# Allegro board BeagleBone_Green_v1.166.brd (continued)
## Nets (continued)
MMC0_DAT1: P10.8(DAT1) R154.2 U5.G15(MMC0_DAT1/GPMC_A22/UART5_CTSN/U)
MMC0_DAT2: P10.1(DAT2) R150.2 U5.F18(MMC0_DAT2/GPMC_A21/UART4_RTSN/T)
MMC0_DAT3: P10.2(CD/DAT3) R155.2 U5.F17(MMC0_DAT3/GPMC_A20/UART4_CTSN/T)
MMC1_CLK: P8.21(11) R110.2 U5.U9(GPMC_CSN1/GPMC_CLK/MMC1_CLK/PRT) U13.M6(CLK)
MMC1_CMD: P8.20(35) R109.2 U5.V9(GPMC_CSN2/GPMC_BE1N/MMC1_CMD/PR) U13.M5(CMD)
MMC1_DAT0: P8.25(13) R101.2 U5.U7(GPMC_AD0/MMC1_DAT0//////GPIO1_0) U13.A3(DAT0)
MMC1_DAT1: P8.24(37) R102.2 U5.V7(GPMC_AD1/MMC1_DAT1//////GPIO1_1) U13.A4(DAT1)
MMC1_DAT2: P8.5(3) R103.2 U5.R8(GPMC_AD2/MMC1_DAT2//////GPIO1_2) U13.A5(DAT2)
MMC1_DAT3: P8.6(28) R104.2 U5.T8(GPMC_AD3/MMC1_DAT3//////GPIO1_3) U13.B2(DAT3)
MMC1_DAT4: P8.23(12) R105.2 U5.U8(GPMC_AD4/MMC1_DAT4//////GPIO1_4) U13.B3(DAT4)
MMC1_DAT5: P8.22(36) R106.2 U5.V8(GPMC_AD5/MMC1_DAT5//////GPIO1_5) U13.B4(DAT5)
MMC1_DAT6: P8.3(2) R107.2 U5.R9(GPMC_AD6/MMC1_DAT6//////GPIO1_6) U13.B5(DAT6)
MMC1_DAT7: P8.4(27) R108.2 U5.T9(GPMC_AD7/MMC1_DAT7//////GPIO1_7) U13.B6(DAT7)
MODE2: R113.1 R138.2 U14.15(COL/CRS_DV/MODE2)
OSC1_IN: C21.2 U5.A6(OSC1_IN) Y1.1
OSC1_OUT: C22.2 U5.A4(OSC1_OUT) Y1.4
P_BYPASS: C4.2 U2.47(BYPASS)
P_INT_LDO: C3.2 U2.48(INT_LDO)
P_L1: L1.1 U2.20(L1)
P_L2: L2.1 U2.23(L2)
P_L3: L3.1 U2.31(L3)
PHY_VDDCR: C134.1 C136.1 U14.6(VDDCR)
PHY_XTAL1: C143.1 R141.2 R142.1 Y3.1
PHY_XTAL2: R141.1 R143.1 U14.4(XTAL2)
PHYX: C142.1 R143.2 Y3.2
PMIC_INT: R1.2 U2.45(INT) U5.B18(NNMI)
PMIC_PGOOD: U2.26(PGOOD) U5.B15(PORZN) U16.2(A)
PMIC_POWR_EN: U2.9(PWR_EN) U5.C6(PMIC_POWER_EN)
PROC_A15: R18.1 U5.A15(EVENT_INTR0/TIMER4/CLKOUT1/SPI1)
PWR_BUT: P9.9(5) S3.2(B1) S3.4(B2) U2.25(PB_IN)
PWR_LEDR: D1.1(C) R12.2
RBIAS: R144.1 U14.32(RBIAS)
RCLKIN: C161.1 R140.2 R142.2 U14.5(XTAL1/CLKIN)
REFCLKO: C162.2 R118.1 R124.2 R131.2 U14.7(RXCLK/PHYAD1)
RXD0/MODE0: R112.1 R128.2 U14.11(RXD0/MODE0)
RXD1/MODE1: R114.1 R127.2 U14.10(RXD1/MODE1)
RXD2/RMIISEL: R117.1 R126.2 U14.9(RXD2/RMIISEL)
RXD3/PHYAD2: R116.1 R125.2 U14.8(RXD3/PHYAD2)
RXDV: R129.2 U14.26(RXDV)
RXER/PHYAD0: R115.1 R133.2 U14.13(RXER/RXD4/PHYAD0)
RXN: C138.1 P5.2(RD-) R121.1 U14.30(RXN)
RXP: C137.1 P5.1(RD+) R120.1 U14.31(RXP)
SPI1_CS0: P9.28(39) U5.C12(MCASP0_AHCLKR/EHRPWM0_SYNCI_O/M)
SPI1_D0: P9.29(15) U5.B13(MCASP0_FSX/EHRPWM0B//SPI1_D0/MM)
SPI1_D1: P9.30(40) U5.D12(MCASP0_AXR0/EHRPWM0_TRIPZONE_IN)
SPI1_SCLK: P9.31(16) U5.A13(MCASP0_ACLKX/EHRPWM0A//SPI1_SCL)
SYS_5V: C7.2 C8.2 C10.2 C13.2 C17.1 C34.1 P9.7(4) P9.8(29) R71.1 R72.1 R73.1 R74.1 U2.2(VINLDO) U2.7(SYS1) U2.8(SYS2) U2.21(VIN_DCDC1) U2.22(VIN_DCDC2) U2.32(VIN_DCDC3) U2.39(LDO3_IN) U2.42(LDO4_IN) U4.2(IN) U8.2(IN1) U8.3(IN2)
SYS_RESETN: C24.1 C30.1 P2.15(SRST) P9.10(30) R14.2 S1.2(B1) S1.4(B2) U5.A10(NRESET_INOUT) U14.19(NRST) U16.4(Y)
TCT_RCT: C141.1 P5.4(RCT) P5.5(TCT) R137.1
TESTOUT: TP3.1(TP) U5.A3(TESTOUT)
TIMER4: P8.7(4) U5.R7(GPMC_ADVN_ALE/TIMER4/GPIO2_2)
TIMER5: P8.9(5) U5.T6(GPMC_BE0N_CLE/TIMER5/GPIO2_5)
TIMER6: P8.10(30) U5.U6(GPMC_WEN/TIMER6/GPIO2_4)
TIMER7: P8.8(29) U5.T7(GPMC_OEN_REN/TIMER7/EMU4/GPIO2_)
TXCLK: R134.2 U14.20(TXCLK)
TXN: C140.1 P5.6(TD-) R123.1 U14.28(TXN)
TXP: C139.1 P5.3(TD+) R122.1 U14.29(TXP)
U5_H18: R28.1 U5.H18(RMII1_REFCLK/XDMA_EVENT_INTR2/S)
U5_R13: R160.1 U5.R13(GPMC_A0/GMII2_TXEN/RGMII2_TCTL/)
U5_T13: R161.1 U5.T13(GPMC_CSN3/MMC2_CMD/PR1_MDIO_DAT)
UART0_RX: U5.E15(UART0_RXD/SPI1_CS0/DCAN0_TX/I2C) U15.6(1Y)
UART0_TX: U5.E16(UART0_TXD/SPI1_CS1/DCAN0_RX/I2C) U15.5(2A)
UART1_RXD: P9.26(38) U5.D16(UART1_RXD/MMC1_SDWP/DCAN1_TX/I2)
UART1_TXD: P9.24(37) U5.D15(UART1_TXD/MMC2_SDWP/DCAN1_RX/I2)
UART2_RXD: J5.1 P9.22(36) U5.A17(SPI0_SCLK/UART2_RXD/I2C2_SDA/EH)
UART2_TXD: J5.2 P9.21(11) U5.B17(SPI0_D0/UART2_TXD/I2C2_SCL/EHRP)
UART4_RXD: P9.11(6) U5.T17(GPMC_WAIT0/GM112_CRS/GPMC_CSN4/)
UART4_TXD: P9.13(7) U5.U17(GPMC_WPN/GMII2_RXERR/GPMC_CSN5/)
USB0_DM: P4.2(D-) U5.N18(USB0_DM) U10.2(D-)
USB0_DP: P4.3(D+) U5.N17(USB0_DP) U10.1(D+)
USB0_ID: P4.4(ID) U5.P16(USB0_ID) U10.3(ID)
USB1_DM: P3.2(P2) U5.R18(USB1_DM) U9.2(D-)
USB1_DP: P3.3(P3) U5.R17(USB1_DP) U9.1(D+)
USB1_DRVVBUS: R53.1 U5.F15(USB1_DRVVBUS/GPIO3_13) U8.4(EN)
USB1_ID: R49.2 U5.P17(USB1_ID)
USB1_OCN: R52.2 U5.T16(GPMC_A10/GMII2_RXD1/RGMII2_RD1/) U8.5(O\C\)
USB1_PWR: C35.1 FB7.1 FB8.2 U8.6(OUT3) U8.7(OUT2) U8.8(OUT1) U9.6(VBUS)
USB1_VBUS: FB8.1 U5.T18(USB1_VBUS)
USB_DC: C1.2 C36.1 P4.1(VB) R159.1 R168.1 U2.12(USB) U10.6(VBUS)
USR0: Q1.2(5) R76.1 U5.V15(GPMC_A5/GMII2_TXD0/RGMII2_TD0/R)
USR1: Q1.5 R77.1 U5.U15(GPMC_A6/GMII2_TXCLK/RGMII2_TCLK)
USR2: Q2.2(5) R78.1 U5.T15(GPMC_A7/GMII2_RXCLK/RGMII2_RCLK)
USR3: Q2.5 R79.1 U5.V16(GPMC_A8/GMII2_RXD3/RGMII2_RD3/M)
VDCDC1: L1.2 R6.1 U2.19(VDCDC1)
VIO: R7.2 U2.18(VIO) U16.5(VCC)
VLDO1: R5.1 R7.1 R8.1 U2.3(VLDO1)
VREFP_ADC: C31.1 C32.1 C33.1 R27.2 U5.B9(VREFP)
VRTC: C16.1 C105.1 R5.2 R26.1 U5.D7(VDDS_RTC)
WAKEUP: R26.2 U2.13(WAKEUP) U5.C5(EXT_WAKEUP)
WP: R156.2 TP4.1(TP) U7.5(WP)
XDMA_EVENT_INTR0: P2.17(EMU2) R18.2
YEL_C: P5.11(YELC) R130.2
YELA: C164.1 C166.1 P5.12(YELA) R135.1 U14.2(LED2/NINTSEL)
ZQ: R99.2 U12.L8(ZQ)
N21757673: C19.1 R10.1 R11.2 U4.4(ADJ)
N21769115: R75.2 S2.1(A1) S2.3(A2)
N22155575: R159.2 U5.P15(USB0_VBUS)
N22248684: R167.1 Y4.3(CLK)
N22287501: R162.1 U3.4(Y)
N22287555: U3.2(A) U5.R14(GPMC_A4/GMII2_TXD1/RGMII2_TD1/R)
N22420400: TP5.1(TP) U2.4(BAT1) U2.5(BAT2)
N22420444: TP6.1(TP) U2.6(BAT_SENSE)
N22420447: TP7.1(TP) U2.11(TS)
N22488252: TP9.1(TP) U5.E17(UART0_RTSN/UART4_TXD/DCAN1_RX/I)
N22648410: C25.1 R17.1 U17.1(XIN/CXIN) Y2.2
N22648422: C26.1 R17.2 U17.2(CKOUT) Y2.1
N22649826: R171.2 U17.3(SSON)
N22650321: R172.2 R174.1 U17.6(ADS0)
N22650344: R173.1 R175.2 U17.7(ADS1)
N22650388: U5.V10(OSC0_IN) U17.5(MOD OUT)

Pads without a net: J1 2 3 6; NOREF#6 1; NOREF#8 1; NOREF#11 1; NOREF#12 1; NOREF#15 1; NOREF#19 1; NOREF#25 1; NOREF#32 1; NOREF#33 1; NOREF#34 1; NOREF#35 1; NOREF#37 1; NOREF#38 1; NOREF#40 1; P2 6; P5 7; U2 14 15 16 17 33 34 35 36 37 38 44; U3 1; U5 E18 F16 M5 M15 P18 U11; U9 3 5; U10 5; U12 J1 J9 L1 L9; U13 A1 A2 A6 A7 A8 A9 A10 A11 A12 A13 A14 B1 B7 B8 B9 B10 B11 B12 B13 B14 C1 C3 C5 C7 C8 C9 C10 C11 C12 C13 C14 D1 D2 D3 D4 D12 D13 D14 E1 E2 E3 E5 E8 E9 E10 E12 E13 E14 F1 F2 F3 F10 F12 F13 F14 G1 G2 G3 G10 G12 G13 G14 H1 H2 H3 H5 H12 H13 H14 J1 J2 J3 J5 J12 J13 J14 K1 K2 K3 K6 K7 K10 K12 K13 K14 L1 L2 L3 L12 L13 L14 M1 M2 M3 M7 M8 M9 M10 M11 M12 M13 M14 N1 N3 N6 N7 N8 N9 N10 N11 N12 N13 N14 P1 P2 P7 P8 P9 P10 P11 P12 P13 P14; U16 1; Y1 2 3

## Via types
v1: diameter 0.457, hole 0.203, TOP to BOTTOM, 820 vias
v2: diameter 0.559, hole 0.305, TOP to BOTTOM, 28 vias

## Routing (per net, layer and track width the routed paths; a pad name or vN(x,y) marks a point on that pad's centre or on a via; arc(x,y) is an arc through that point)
DGND: length 353.8
  TOP w0.076: U13.N2 28.49,109.79 28.23,110.04 27.89,110.04 27.88,110.05 27.73,110.05
  TOP w0.178: U13.N5 U13.P4
  TOP w0.191: U10.4 v1(15.49,106.54)
  TOP w0.203: 27.73,110.05 27.57,110.05 v1(27.41,110.21) ; U13.C4 v1(32.99,108.29) ; U13.K8 v1(29.46,106.79) ; v1(31.24,105.18) 31.24,105.26 30.99,105.51 U13.H10 ; U13.E7 32.67,107.11 v1(32.99,107.11) ; v2(25.27,80.37) 25.65,80.37 25.85,80.17 U2.30 ; U13.G5 31.35,108.43 31.19,108.59 v1(31.19,108.81) ; v1(27.43,107.65) 27.57,107.79 U13.P6 ; U2.41 v1(24.86,84.75) ; U13.P4 26.98,108.79 v1(26.49,109.27)
  TOP w0.254: U12.B9 v1(68.5,95.49) U12.A9 ; U5.H7 v1(49.52,92.74) ; v1(47.92,95.14) U5.K9 ; v1(68.5,85.09) U12.P9 ; U5.L12 v1(44.72,95.94) U5.L13 ; U5.J11 v1(45.52,93.54) ; v1(44.72,92.74) U5.H12 ; U5.A18 v1(39.92,87.13) ; v1(67.7,93.09) U12.E8 ; U5.M9 v1(47.92,96.74) U5.M8 ; U5.F8 v1(47.92,91.94) U5.G9 ; v1(61.3,95.49) U12.B1 ; U12.G1 60.71,92.08 60.71,92.43 61.09,92.81 61.58,92.81 U12.E1 v1(62.1,92.29) ; v1(68.5,86.69) U12.M9 ; v1(54,101.7) 53.92,101.62 U5.V1 ; v1(44.72,91.94) U5.G12 45.28,92.18 45.76,92.18 U5.G11 ; U5.A1 v1(53.92,86.84) ; v1(46.32,96.74) U5.M10 ; v1(48.72,93.54) U5.J8 ; U5.L10 v1(46.32,95.14) ; v1(46.32,95.14) U5.K10 ; v1(46.32,95.14) U5.K11 ; U12.F9 v1(68.5,91.49) U12.G9 ; v1(48.72,92.74) U5.H8 ; v1(62.1,89.09) U12.J2 ; U5.G8 v1(47.92,92.74) U5.H9 ; U5.M12 v1(45.52,95.94) U5.L11 ; v1(61.3,86.69) U12.M1 ; v1(47.92,93.54) U5.J9 ; U5.N10 v1(46.32,97.54) U5.N11 ; v1(62.9,95.49) U12.B3 ; v1(61.3,83.49) U12.T1 ; U12.D1 v1(62.1,93.09) U12.E2 ; U5.M7 v1(49.52,95.94) U5.M6 ; v1(67.7,91.49) U12.G8 ; v1(49.52,93.54) U5.J7 U5.K7 ; U5.H10 v1(46.32,93.54) U5.J10 ; U5.H6 v1(50.32,93.54) U5.J6 ; v1(68.5,83.49) U12.T9 ; v1(49.52,97.54) U5.N7 ; U5.N14 v1(43.12,96.74) U5.M14 ; U5.V18 40.39,101.2 v1(40.39,101.96) ; v1(67.7,93.89) U12.D8 ; v1(61.3,85.09) U12.P1 ; v1(67.7,89.09) U12.J8
  TOP w0.381: C57.1 v1(56.26,113.64) ; C162.1 R118.2 31.93,90.02 v1(32.08,89.87) ; v1(79.8,80.67) J4.4 v1(75.77,80.67) ; 40.13,104.75 40,104.88 C159.2 38.99,104.88 38.73,105.13 ; S1.1 v1(9.35,116.48) ; C153.2 84.2,108.69 v1(84.46,108.94) ; v1(28.38,72.24) 28.38,73.32 C12.1 28,73.44 27.69,73.13 27.69,72.3 v1(27.75,72.24) ; R170.2 23.01,102.82 v1(22.71,103.12) ; v1(23.49,86.46) 22.86,85.83 22.86,85.45 ; v1(54.48,107.8) 54.36,107.92 R81.2 ; v1(57.4,76.53) 57.12,76.81 57.02,76.81 C155.1 C96.1 57.89,77.95 57.91,77.93 ; C18.2 v1(19.68,84.68) ; v1(17.32,108.99) 17.81,108.99 18.02,108.78 Q2.1 ; v1(22.99,72.36) 22.99,73.25 C1.1 22.35,73.38 v1(22.35,72.36) ; C154.2 v1(80.14,108.56) ; R94.2 75.57,111.35 v1(75.18,110.97) ; S3.1 9.35,108.89 v1(10.03,109.58) ; S2.4 v1(73.53,107.87) ; Q1.1 20.69,108.75 v1(19.96,109.47) 19.84,109.6 19.48,109.6 19.32,109.76 Q2.4 ; 23.37,108.18 R77.2 23.11,109.58 22.73,109.96 22.73,110.46 v1(22.61,110.59) 22.1,110.59 21.99,110.48 Q1.4 ; S3.3 v1(10.29,104.85) ; v1(73.15,110.85) 73.79,111.48 R92.2 R93.2 ; R78.2 R79.2 21.97,105.23 v1(22.48,104.72) ; U3.3 v1(42.37,110.85) ; v1(35.69,71.6) C29.2 ; R25.2 37.78,74.21 37.46,73.89 v1(37.46,73.7) ; R80.2 v1(55.37,110.97) ; U16.3 32.28,74.81 32.05,75.03 v1(31.65,75.03) ; S1.3 v1(9.35,115.6) ; v1(47.75,77.71) R165.2 ; C61.1 v1(76.45,113.51) ; v1(77.85,110.85) 77.34,111.35 R95.2 ; R84.2 v1(57.66,110.85) ; S2.2 v1(77.09,107.87) ; J5.4 v1(79.93,95.53)
  TOP w0.889: Y4.2 42.18,107.79 ; Y4.2 42.82,107.23 ; Y4.2 42.18,106.67
  LYR2_GND w0.889: 76.23,67.76 P9.45 77.7,67.76 ; 11.02,72.77 P3.4 ; P3.4 12.34,74.1 ; P3.4 11.02,74.1 ; P3.4 12.34,72.77 ; 17.81,91.26 P5.8 ; P5.8 19.28,91.26 ; P5.8 19.28,89.79 ; P5.8 17.81,89.79 ; 42.98,73.71 J1.1 ; J1.1 42.98,71.78 ; J1.1 44.91,71.78 ; P8.1 22.05,116.26 ; P8.1 22.05,114.32 ; P8.1 20.12,116.26 ; P8.1 20.12,114.32 ; P9.2 21.82,68.84 ; P9.2 20.35,70.3 ; P9.2 21.82,70.3 ; P9.2 20.35,68.84 ; 20.12,68 P9.1 22.05,68 ; P9.44 75.16,70.3 ; P9.44 73.69,68.84 ; P9.44 73.69,70.3 ; P9.44 75.16,68.84 ; 60.84,76.53 TP1.1 ; TP1.1 62.3,75.06 ; TP1.1 62.3,76.53 ; TP1.1 60.84,75.06 ; 75.16,67.76 P9.43 73.69,67.76 ; 21.82,117.1 P8.2 20.35,117.1 ; TP8.1 19.4,72.52 ; TP8.1 19.4,73.99 ; TP8.1 17.94,72.52 ; TP8.1 17.94,73.99 ; 76.23,70.3 P9.46 ; P9.46 77.7,70.3 ; P9.46 76.23,68.84 ; P9.46 77.7,68.84
  LYR5_PWR w0.889: 73.69,70.3 P9.44 ; P9.44 73.69,68.84 ; P9.44 75.16,68.84 ; P9.44 75.16,70.3 ; P9.46 77.7,68.84 ; P9.46 76.23,68.84 ; P9.46 76.23,70.3 ; P9.46 77.7,70.3 ; 76.23,67.76 P9.45 77.7,67.76 ; 73.69,67.76 P9.43 75.16,67.76
  BOTTOM w0.191: v1(30.61,97.83) 30.61,97.48 30.73,97.35 32.26,97.35 32.38,97.22 R115.2 ; v1(46.32,89.54) 46.32,89.42 47.11,88.63 C88.2
  BOTTOM w0.203: C100.2 50.21,91.07 50.66,90.62 50.83,90.62 v1(51.12,90.34)
  BOTTOM w0.254: 54.52,82.35 R30.1 53.68,82.35 ; v1(57.4,76.53) 57.4,76.81 57.15,77.06 C155.1 ; C130.2 36.37,105.84 v1(36.98,105.84) ; C70.1 44.02,91.24 v1(44.72,91.94) v1(44.72,92.74) ; v1(14.22,80.87) 14.61,80.48 U9.4 ; C127.2 v1(26.8,105.77) ; U15.1 51.68,75.81 51.43,76.05 51.43,77.06 51.68,77.3 U15.4 53.48,77.3 54.23,76.56 54.23,75.67 54.61,75.29 v1(55.88,75.29) ; C129.2 32.51,106.53 32.99,107.01 v1(32.99,107.11) ; 15.49,82.14 v1(14.61,82.14) ; v1(29.46,106.79) 29.49,106.81 29.62,106.81 30.35,107.54 C128.2
  BOTTOM w0.305: v1(46.32,93.54) 46.98,93.54 C49.2 ; C47.2 47.22,95.14 v1(47.92,95.14) ; C94.2 v1(45.52,95.94) ; C98.2 50.32,94.23 v1(50.32,93.54) ; v2(52.32,110.46) R29.1 v2(53.09,111.35) ; v1(46.32,95.14) 46.02,94.84 C46.2 ; C41.2 43.12,97.43 v1(43.12,96.74) 43.12,96.04 C66.2 ; C50.2 v1(48.72,92.74) ; v1(47.92,96.74) 47.62,97.03 C42.2 ; C63.2 45.41,91.94 v1(44.72,91.94) ; C72.1 47.62,91.64 v1(47.92,91.94) ; C43.2 48.83,97.54 v1(49.52,97.54) C73.1 ; C48.2 49.23,93.83 v1(49.52,93.54) ; v1(49.52,95.94) C97.2 ; C99.2 v1(49.52,92.74) ; C60.1 v1(44.72,92.74)
  BOTTOM w0.381: v1(6.99,74.9) 6.73,74.9 6.31,74.48 U8.1 ; v1(50.61,83.54) C104.2 C92.2 ; v1(50.61,83.54) 52.27,83.54 52.51,83.79 R54.1 ; v1(50.61,83.54) R164.2 ; v1(37.46,81.32) P2.16 39.41,81.25 40.75,81.25 40.89,81.11 41.63,81.11 41.93,81.4 41.93,82.89 40.96,83.86 P2.20 ; C80.2 42.72,102.9 42.75,102.93 v1(42.75,103.12) ; C68.1 v1(50.32,103.23) ; v1(20.09,113.74) 19.56,113.21 U4.6 ; v1(24.99,105.16) 24.89,105.26 C126.1 ; 27.3,95.61 27.56,95.35 C136.2 ; v1(33.78,102.27) C77.2 ; C141.2 v1(12.06,95.61) ; C28.2 v1(58.55,93.54) ; v1(36.96,99.03) 36.45,99.03 C78.2 ; v1(3.3,82.91) 3.68,82.52 R12.1 ; C17.2 21.72,103.15 v1(21.18,102.62) ; C122.1 71.24,81.95 v1(71.25,81.95) ; C135.2 29.21,98.78 29.24,98.76 v1(29.39,98.76) ; v1(20.27,102.51) 20.57,102.82 C20.2 ; R88.2 v1(66.42,108.43) ; C75.1 v1(54.48,113.51) ; v1(19.53,114.58) 19.3,114.58 18.29,113.56 U4.5 ; R100.2 C124.2 v1(64.39,86.33) ; U7.2 31.31,87.03 30.86,86.59 v1(30.86,85.83) ; C112.2 v1(58.55,85.89) ; C71.1 40.26,102.08 v1(40.39,101.96) ; 34.42,85.45 35.18,85.45 ; 34.42,85.45 34.42,86.33 C62.1 35.18,86.33 35.18,85.45 ; 34.42,85.45 v1(34.42,85.45) ; 35.18,85.45 C64.2 ; C117.2 70.75,90.69 v1(71.27,90.17) ; C120.2 v1(71.25,85.89) ; C45.2 C87.2 38.95,95.9 38.26,95.9 v1(38.23,95.94) ; v1(17.93,102.54) 17.53,102.95 R10.2 ; U4.7 v1(20.83,113.51) ; C119.2 v1(71.25,89.49) ; v1(13.46,98.78) 13.42,98.78 13.17,99.03 13.17,99.2 C137.2 ; P10.9 v1(73.99,99.07) ; C116.2 v1(71.37,93.7) ; C24.2 C30.2 31.39,75.29 v1(31.65,75.03) ; C142.2 v1(23.3,90.4) ; C92.2 v1(49.66,83.65) ; C92.2 C105.2 C89.2 C91.2 C90.2 C59.2 ; C158.2 41.91,112.62 42.37,112.16 v1(42.37,110.85) ; C161.2 28.57,92.3 v1(29.34,92.3) ; R53.2 v1(4.32,70.33) ; C111.2 v1(58.55,88.29) ; P2.4 v1(37.46,73.7) ; v1(7.62,95.35) 6.79,95.35 R136.1 6.79,94.59 v1(7.62,94.59) ; v1(7.62,95.35) v1(7.62,94.59) ; v1(7.62,95.35) R132.1 ; v1(51.56,103.23) 51.92,102.87 C74.1 ; v1(7.62,94.59) R130.1 R135.2 ; C35.2 v1(7.49,81.13) ; C113.2 v1(58.55,84.29) ; R96.1 v1(71.25,88.29) ; C125.2 v1(33.78,113.39) ; R145.2 v1(33.15,99.73) ; P2.8 37.53,76.24 v1(37.46,76.3) 37.46,77.26 37.71,77.51 P2.10 P2.12 ; C86.2 38.98,100.37 38.61,100.74 38.15,100.74 v1(38.1,100.79) ; R83.2 62.1,108.66 v1(62.41,108.36) ; R82.2 60.81,109.19 v1(60.5,108.89) ; C58.2 C106.2 45.36,102.44 45.85,101.96 v1(47.12,101.96) C56.1 ; C54.2 C79.2 C69.1 ; C54.2 v1(38.23,91.94) ; C54.2 C44.2 ; C61.1 v1(76.45,113.51) ; v1(14.07,108.81) C36.2 14.86,109.32 v1(14.61,109.58) ; R87.2 v1(65.53,108.43) ; C84.2 48.39,102.9 v1(48.72,103.23) 49.28,102.67 C81.2 ; R99.1 v1(71.25,87.09) ; v1(67.7,89.09) U12.J8 C123.2 ; v1(38.23,98.78) 38.54,99.1 R49.1 ; v1(34.42,100.69) C67.2 C38.2 ; v1(71.32,91.06) 71.5,91.24 C118.1 ; C108.2 v1(58.55,94.69) ; R30.1 C102.2 ; R89.2 v1(67.69,108.46) ; C121.2 v1(71.25,84.29) ; v1(4.47,110.82) 4.78,110.52 6.08,110.52 P4.5 ; R117.2 R116.2 v1(33.15,93.07) ; C110.2 v1(58.55,90.69) 58.46,90.78 R22.1 ; C114.2 v1(71.25,96.29) ; v1(16.74,76.94) C2.1 16.18,78.03 15.67,77.52 v1(15.67,76.99) ; C85.2 C83.2 C82.2 38.35,89.89 38.23,90.01 v1(38.23,90.01) ; C139.2 v1(12.06,96.88) ; C138.2 v1(12.06,98.15) ; C109.2 v1(58.55,92.29) ; C19.2 18.41,102.92 v1(18.82,102.51) ; R85.2 v1(63.37,108.46) ; R91.2 v1(69.16,109.19) R90.2 ; C115.2 v1(71.25,94.69) ; R86.2 v1(64.26,108.36) ; P10.6 v1(84.39,96.71) ; R144.2 v1(20.13,93.38) ; C140.2 v1(12.06,93.07) ; C152.2 v1(27.43,88.24) ; U4.8 v1(22.1,113.51) ; C107.2 v1(58.55,96.29) ; 44.83,79.99 v1(44.83,79.22) v1(45.59,79.22) 45.59,79.99 FB3.2 44.83,79.99
  BOTTOM w0.762: P8.1 P8.2 ; P9.45 P9.46 ; P9.1 P9.2
  vias: v1(5.21,97.26) v1(8.38,93.83) v1(11.71,109.58) v1(14.5,84.51) v1(14.53,83.29) v1(17.02,81.38) v1(23.3,91.48) v1(26.04,89.59) v1(29.72,89.64) v1(29.97,67.26) v1(31.37,83.16) v1(31.37,82.52) v1(32.46,67.21) v1(34.42,92.49) v1(34.42,91.67) v1(34.42,89.51) v1(41.4,107.9) v1(42.04,104.75) v1(54.23,83.54) v1(56.77,81.89) v1(60.12,100.23) v1(62.23,100.18) v1(63.12,74.14) v1(63.25,76.17) v1(64.47,100.2) v1(64.57,80.95) v1(65.41,73.38) v1(66.8,75.8) v1(66.9,81) v1(67.95,100.13) v1(68.96,73.38) v1(70.97,103.86) v1(70.99,102.54) v1(70.99,101.09) v1(71.5,73.38) v1(72.26,78.46) v1(72.9,71.35) v1(75.95,78.46) v1(76.2,71.35) v1(78.36,103.1) v1(81.03,103.99) v1(82.42,78.84) v1(82.55,87.48) v1(82.55,84.43) v1(82.55,80.62) v1(82.93,97.89) v1(83.19,102.21) v1(83.19,100.56) v1(83.31,91.16) v1(84.96,102.36) v1(84.96,100.61) v1(84.99,98.48) v1(84.96,83.03) v1(85.09,79.73) v1(85.22,87.22) v1(85.73,91.03) v2(4.7,76.81) v2(4.7,75.54) v2(5.97,76.81) v2(5.97,75.54) v2(22.48,80.75) v2(22.73,78.71) v2(24,80.37) v2(24,79.1) v2(25.53,96.24) v2(26.48,97.19) v2(26.48,96.24) v2(26.48,95.29) v2(27.43,96.24)
GND_EARTH: length 295.5
  TOP w0.889: 2.23,106.75 P4.8 2.23,105.33 ; 14.24,118.33 MTG3.1 ; MTG3.1 17.77,118.33 ; MTG3.1 17.77,114.79 ; 80.28,111.62 MTG4.1 ; MTG4.1 83.81,115.15 ; MTG4.1 83.81,111.62 ; MTG4.1 80.28,115.15 ; 80.28,73.24 MTG2.1 ; MTG2.1 80.28,69.71 ; MTG2.1 83.81,69.71 ; MTG2.1 83.81,73.24 ; 2.23,111.77 P4.9 2.23,113.19 ; MTG1.1 17.77,70.07 ; MTG1.1 14.24,70.07 ; MTG1.1 14.24,66.53 ; MTG1.1 17.77,66.53
  LYR2_GND w0.889: MTG1.1 17.77,70.07 ; MTG1.1 14.24,70.07 ; MTG1.1 14.24,66.53 ; MTG1.1 17.77,66.53 ; 2.23,106.75 P4.8 2.23,105.33 ; 80.28,73.24 MTG2.1 ; MTG2.1 83.81,73.24 ; MTG2.1 83.81,69.71 ; MTG2.1 80.28,69.71 ; MTG3.1 17.77,118.33 ; MTG3.1 14.24,118.33 ; MTG3.1 17.77,114.79 ; MTG4.1 83.81,111.62 ; MTG4.1 83.81,115.15 ; MTG4.1 80.28,111.62 ; MTG4.1 80.28,115.15 ; 2.23,113.19 P4.9 2.23,111.77
  LYR3 w0.889: 2.23,105.33 P4.8 2.23,106.75 ; 14.24,66.53 MTG1.1 ; MTG1.1 17.77,66.53 ; MTG1.1 17.77,70.07 ; MTG1.1 14.24,70.07 ; 2.23,113.19 P4.9 2.23,111.77 ; MTG4.1 83.81,111.62 ; MTG4.1 80.28,115.15 ; MTG4.1 80.28,111.62 ; MTG4.1 83.81,115.15 ; MTG2.1 83.81,73.24 ; MTG2.1 83.81,69.71 ; MTG2.1 80.28,73.24 ; MTG2.1 80.28,69.71 ; MTG3.1 17.77,114.79 ; MTG3.1 14.24,118.33 ; MTG3.1 17.77,118.33
  LYR4 w0.889: 80.28,73.24 MTG2.1 ; MTG2.1 83.81,73.24 ; MTG2.1 83.81,69.71 ; MTG2.1 80.28,69.71 ; MTG1.1 17.77,66.53 ; MTG1.1 14.24,70.07 ; MTG1.1 14.24,66.53 ; 2.23,106.75 P4.8 2.23,105.33 ; 2.23,111.77 P4.9 2.23,113.19 ; MTG4.1 83.81,115.15 ; MTG4.1 80.28,111.62 ; MTG4.1 83.81,111.62 ; MTG4.1 80.28,115.15 ; MTG3.1 17.77,118.33 ; MTG3.1 14.24,118.33 ; MTG3.1 17.77,114.79
  LYR4 w1.016: P3.5 9.11,83.51 12.7,87.1 ; P3.6 v1(8.97,67.46)
  LYR5_PWR w0.889: MTG3.1 17.77,118.33 ; MTG3.1 14.24,118.33 ; MTG3.1 17.77,114.79 ; MTG2.1 83.81,69.71 ; MTG2.1 80.28,69.71 ; MTG2.1 80.28,73.24 ; MTG2.1 83.81,73.24 ; 14.24,70.07 MTG1.1 ; MTG1.1 17.77,66.53 ; MTG1.1 14.24,66.53 ; MTG1.1 17.77,70.07 ; 80.28,111.62 MTG4.1 ; MTG4.1 83.81,111.62 ; MTG4.1 80.28,115.15 ; MTG4.1 83.81,115.15 ; 2.23,105.33 P4.8 2.23,106.75 ; 2.23,111.77 P4.9 2.23,113.19
  BOTTOM w0.381: v1(79.63,110.72) 79,110.09 P10.11 ; P4.6 5.95,113.81 ; C164.2 10.41,91.8 10.79,91.41 ; 73.76,106.3 73.73,106.27 P10.15 72.5,105.12 72.47,105.08 ; 5.95,104.42 v1(5.28,103.76) ; 5.95,104.42 v1(6.63,103.74) ; 5.95,104.42 P4.7 ; v1(3.3,94.59) 4.25,94.59 R136.2 4.25,95.35 v1(3.3,95.35) ; P10.13 v1(86.36,109.07) ; P10.12 77.84,95.59 ; 73.37,100.27 P10.16 ; C166.2 9.27,91.54 ; P10.14 v1(86.36,96.67)
  BOTTOM w0.508: 7.43,103.54 7.49,103.61 ; P5.13 12.06,102.21 12.06,99.42 10.03,97.38 C163.2 C165.2
  BOTTOM w0.889: 75.36,109.45 P10.11 74.15,110.09 ; 2.23,111.77 P4.9 ; P4.9 4.17,111.77 ; P4.9 2.23,113.19 ; MTG4.1 83.81,111.62 ; MTG4.1 83.81,115.15 ; MTG4.1 80.28,115.15 ; MTG4.1 80.28,111.62 ; 76.66,94.95 P10.12 ; P10.12 75.45,95.59 ; P10.12 76.66,96.24 ; 14.24,70.07 MTG1.1 ; MTG1.1 17.77,70.07 ; MTG1.1 17.77,66.53 ; MTG1.1 14.24,66.53 ; P4.8 4.17,105.33 ; P4.8 2.23,105.33 ; P4.8 4.17,106.75 ; P4.8 2.23,106.75 ; 80.28,69.71 MTG2.1 ; MTG2.1 83.81,69.71 ; MTG2.1 83.81,73.24 ; MTG2.1 80.28,73.24 ; MTG3.1 17.77,114.79 ; MTG3.1 17.77,118.33 ; MTG3.1 14.24,118.33
  vias: v1(2.59,110.74) v1(2.84,115.11) v1(86.31,102.03) v1(86.28,97.31) v1(86.39,105.26)
GND_OSC0: length 9.4
  TOP w0.381: v2(45.59,104.75) 45.92,104.43 U5.V11
  BOTTOM w0.305: R29.2 C25.2 ; R29.2 53.85,109.45 ; R29.2 52.45,109.45 ; U17.4 49.49,105.17 49.53,105.13 ; R173.2 45.47,108.43
  BOTTOM w0.381: R173.2 44.7,107.54 ; R174.2 44.45,104.11
GND_OSC1: length 7.3
  TOP w0.254: 51.43,86.59 50.72,87.31 U5.A5
  BOTTOM w0.381: v1(51.31,80.11) 51.88,80.68 C21.1 52.51,80.81 ; C22.1 52.51,80.81 ; C22.1 v1(53.15,79.98) ; C22.1 R30.2 ; 52.51,80.81 v1(52.51,82.91)
GNDA_ADC: length 46.4
  TOP w0.254: v1(48.72,90.34) U5.E8
  TOP w0.305: 47.52,87.1 U5.A9
  TOP w0.381: 47.52,87.1 47.52,87.08 47.88,86.72 47.88,83.03 47.24,82.4 C93.2 ; C93.2 C33.2 C31.2 C32.2 ; C93.2 v1(46.48,81.64)
  LYR4 w0.381: P9.34 60.64,68.49 58.73,68.49 57.91,69.31 57.91,69.95 55.35,72.51 55.35,73.03 54.41,73.96 52.96,73.96 52.63,74.3 51.16,74.3 49.23,76.23 49.23,78.99 46.58,81.64 v1(46.48,81.64) 46.48,84.05 47.88,85.45 47.88,87.73 47.24,88.37 47.24,89.89 47.69,90.34 v1(48.72,90.34)
  BOTTOM w0.381: FB3.1 46.23,82.27 46.48,82.02 v1(46.48,81.64)
VBUS: length 4.9
  BOTTOM w0.629: 10.82,81.3 P3.1 ; P3.1 12.54,79.57 ; P3.1 10.82,79.57 ; P3.1 12.54,81.3
VDD_1V8: length 35.5
  TOP w0.203: 25.67,84.94 25.22,84.48 25.22,83.99 25.26,83.95 U2.40
  TOP w0.254: v1(41.52,97.54) U5.N16 ; U5.E9 U5.D10 v1(46.32,90.34) ; U5.R16 41.54,99.11 v1(41.48,99.11)
  TOP w0.381: 25.67,84.94 26.86,84.94 v1(28.32,83.48) v1(28.32,82.84)
  LYR3 w0.381: v1(28.32,82.84) v1(28.32,83.48)
  BOTTOM w0.305: v1(46.32,90.34) 47.01,89.64 C88.1 ; C86.1 40.09,100.37 40.52,99.93 40.72,99.93 41.15,99.5 41.15,99.43 v1(41.48,99.11)
  BOTTOM w0.381: 18.8,83.92 19.94,83.92 21.46,85.45 25.91,85.45 26.8,84.56 26.8,83.48 C14.2 ; C14.2 27.43,82.84 v1(28.32,82.84) v1(28.32,83.48) 27.43,83.48 C14.2 ; v1(34.42,99.03) 34.92,99.03 C78.1 34.8,98.4 v1(34.42,98.4) 34.42,98.02 35.18,97.26 FB1.1 ; FB2.2 47.75,79.57 47.37,79.18 v1(47.28,79.18) 46.49,79.18 v1(46.46,79.22) 46.46,79.25 46.48,79.27 46.48,80.11 46.74,80.37 FB2.2
VDD_3V3A: length 117.8
  TOP w0.203: v1(23.76,84.75) 23.76,84.23 24.06,83.93 U2.43
  TOP w0.254: U5.P11 v1(46.32,98.34) U5.P10 ; U5.N5 v1(51.12,96.74) ; v1(49.52,98.34) U5.P7 U5.P8 ; U5.E13 v1(44.72,90.34) U5.E12 v1(45.52,90.34) U5.E11 v1(46.32,91.14) U5.E10 ; U5.J14 v1(43.12,93.54) U5.H14 ; U5.P6 v1(50.32,98.34) ; U5.P13 v1(43.92,98.34) ; U5.L14 v1(43.92,95.14) U5.K14 ; v1(42.32,97.54) U5.N15 ; U5.P12 v1(44.72,98.34) ; U5.P5 v1(51.12,98.34) ; U5.F14 v1(43.12,91.94) U5.G14 ; v1(42.3,99.15) U5.R15
  TOP w0.381: v1(41.08,110.86) 41.07,110.88 U3.5 ; C61.2 76.45,111.35 v1(76.96,110.85) ; R3.1 R4.1 ; R4.1 C37.1 ; R4.1 v1(28.38,88.24) ; R169.2 23.75,106.02 24.05,105.71 v1(24.05,105.21) ; v1(38.73,105.66) 38.88,105.66 39.12,105.89 C159.1 40,105.89 40.32,105.58 Y4.4 ; v1(57,111.73) C57.2 ; v1(25.78,86.46) 25.02,85.7 R1.1 ; v1(54.48,110.97) R56.1
  LYR3 w0.381: v1(24.05,105.21) 24.05,104.98 24.59,104.44 35.97,104.44 36.75,103.66 v1(37.52,103.66) ; v1(3.1,81.94) 3.66,81.38 4.45,81.38 6.99,78.84 10.54,78.84 10.79,79.1 12.32,79.1 13.21,79.98 16.69,79.98 17.91,81.2 17.91,83.03 18.41,83.54 22.73,83.54 23.76,84.56 v1(23.76,84.75)
  BOTTOM w0.305: v1(46.32,98.34) 47.01,99.03 C56.2 ; v1(43.92,95.14) 44.02,95.24 C66.1 ; v2(46.48,108.43) R175.1 46.86,107.54 47.13,107.28 U17.8 ; v1(43.12,93.54) 43.12,92.84 C60.2 43.12,92.63 v1(43.12,91.94) 43.12,91.24 C70.2 ; v1(42.32,97.54) 41.31,96.53 41.21,96.53 40.54,95.86 C87.1 ; C72.2 46.82,90.63 v1(46.32,91.14)
  BOTTOM w0.381: R14.1 31.37,77.19 v1(31.62,77.44) ; R156.1 C152.1 28.38,86.53 ; v1(28.38,88.24) 28.38,86.53 ; 28.38,86.53 28.83,86.08 U7.4 ; U4.1 22.1,105.66 22.48,105.28 23.98,105.28 v1(24.05,105.21) ; v1(76.96,110.85) 77.34,111.23 R70.1 C61.2 R69.1 R68.1 R67.1 R66.1 v1(69.77,110.92) ; R55.1 R56.1 v1(54.48,110.97) ; C15.2 23.37,84.05 23.76,84.44 v1(23.76,84.75) ; R63.1 66.42,111.25 v1(66.01,110.85) 66.01,110.97 65.53,111.46 R62.1 ; R61.1 64.26,111.38 v1(63.86,110.97) 63.37,111.46 R60.1 ; R52.1 3.66,81.38 v1(3.1,81.94) ; R64.1 67.69,111.43 v1(68.15,110.97) 68.58,111.4 R65.1 ; C77.1 36.58,103 37.24,103.66 v1(37.52,103.66) ; C77.1 36.2,101.89 C67.1 ; C77.1 36.89,101.96 v1(37.48,101.96) ; v1(41.08,110.86) C158.1 ; C59.1 v1(44.89,86.08) ; v2(44.75,106.06) 44.83,105.98 44.83,105.89 45.21,105.51 R172.1 ; C71.2 39.24,102.08 v1(39.37,101.96) ; C73.2 51.23,96.84 v1(51.12,96.74) ; C67.1 C38.1 ; C67.1 v1(36.96,100.69) ; R59.1 v1(57,111.73) ; v2(50.16,105.38) 50.38,105.38 50.54,105.22 50.58,105.22 50.8,105 R171.1 ; R58.1 62.1,111.38 v1(61.67,110.95) 61.21,111.4 R57.1
VDD_3V3AUX: length 19.4
  TOP w0.203: 20.6,82.95 20.98,82.57 U2.1
  TOP w0.381: 20.6,82.95 20.6,84.94 20.7,85.04 C18.1 20.7,85.83 19.94,86.59 14.99,86.59 13.78,85.38 12.13,85.38 11.86,85.65 D1.2
VDD_3V3B: length 131.4
  TOP w0.203: v1(30.32,105.21) 30.33,105.22 30.33,105.36 30.49,105.52 U13.J10 ; U13.C6 33.11,107.79 33,107.68 v1(32.99,107.68) 32.6,107.68 U13.E6 ; U13.F5 31.99,108.57 v1(31.75,108.81) ; v1(27.38,109.29) U13.P3 U13.N4 ; v1(29.46,105.94) 29.46,105.95 29.46,105.96 29.46,106.05 29.7,106.29 U13.K9 ; U13.P5 26.77,108.29 v1(26.72,108.33) ; U13.M4 v1(29.46,108.79)
  TOP w0.254: U14.12 29.4,95.99 v1(29.84,95.99)
  TOP w0.381: C29.1 v1(35.69,74.97) 36.26,75.54 38.23,75.54 38.86,76.17 38.86,77.76 38.61,78.02 R23.1 38.23,79.22 ; R119.1 v1(33.15,98.78)
  TOP w0.635: v2(75.64,98.2) 76.31,97.53 J5.3 ; J4.3 v2(79.94,82.67)
  LYR3 w0.381: v1(56.77,75.29) 56.77,74.78 56.47,74.48 48.31,74.48 47.6,75.18 42.85,75.18 42.45,74.78 41.02,74.78 40.83,74.97 v1(35.69,74.97)
  LYR4 w0.381: v1(56.77,75.29) 56.77,77.19 55.75,78.21 v1(55.75,79.36)
  LYR4 w0.635: v2(76.73,104.65) 75.64,103.56 v2(75.64,98.2) 75.64,94.18 v2(78.69,91.14) 79.94,89.88 v2(79.94,82.67)
  LYR5_PWR w0.889: 24.36,67.76 P9.3 22.89,67.76 ; 22.89,70.3 P9.4 ; P9.4 24.36,70.3 ; P9.4 24.36,68.84 ; P9.4 22.89,68.84
  BOTTOM w0.191: v1(29.84,95.99) 30.25,96.4 32.26,96.4 32.38,96.27 R112.2
  BOTTOM w0.254: C127.1 26.8,108.25 v1(26.72,108.33) ; v1(31.75,108.81) 31.95,108.62 31.95,108.26 31.88,108.19 C129.1 32.27,107.54 32.4,107.68 v1(32.99,107.68) ; v1(29.46,105.94) 29.46,105.95 29.46,106.03 29.72,106.29 29.97,106.29 30.21,106.53 C128.1 30.61,105.88 30.49,105.77 30.49,105.52 30.33,105.36 30.33,105.22 v1(30.32,105.21) ; C130.1 35.15,107.54 v1(35.1,107.59) ; U15.7 56.51,76.31 C155.2 56.53,75.81 U15.8
  BOTTOM w0.381: v2(78.69,91.14) 79.27,91.72 79.3,91.72 79.63,92.05 R154.1 R153.1 R152.1 ; R102.1 v1(47.75,110.85) ; v1(85.28,106.59) 85.09,106.78 P10.4 ; R105.1 v1(49.02,110.85) ; v1(29.84,95.99) 27.56,98.28 C135.1 ; R163.1 49.34,79.67 49.66,79.35 55.74,79.35 v1(55.75,79.36) ; R103.1 v1(27.43,110.85) ; C155.2 v1(56.77,75.29) ; R11.1 19.56,103.23 19.94,103.61 v1(19.94,103.73) 19.94,103.86 20.32,104.24 C20.1 20.57,104.88 19.56,105.89 U4.3 ; R110.1 v1(46.48,110.85) ; v1(72.16,107.29) R157.2 ; R104.1 v1(28.7,110.85) ; R119.1 v1(33.15,98.78) ; R106.1 v1(45.21,110.85) ; R111.1 v1(30.61,113.39) ; P2.5 v1(35.69,74.97) ; C126.2 v1(24.89,109.07) ; R108.1 v1(26.16,110.85) ; R109.1 v1(43.94,110.85) ; R101.1 v1(50.29,110.85) ; R107.1 v1(24.89,110.85) ; R114.2 R112.2
  BOTTOM w0.762: P9.3 P9.4
  vias: v1(27.11,101) v1(80.9,106.02)
VDD_5V: length 8.1
  TOP w0.203: U2.10 20.32,78.97
  LYR4 w0.889: P9.5 26.9,67.76 ; P9.5 25.43,67.76 ; P9.5 26.9,66.3 ; 25.43,68.84 P9.6 ; P9.6 26.9,70.3 ; P9.6 26.9,68.84 ; P9.6 25.43,70.3
  vias: v1(19.43,78.21) v1(19.43,77.5)
VDD_ADC: length 33.1
  TOP w0.254: v1(48.72,89.54) U5.D8
  TOP w0.381: v1(47.24,83.54) 47.12,83.41 C93.1 46.48,84.46 R27.1 47.24,85.22 47.24,86.07 v1(47.24,86.08)
  LYR3 w0.381: v1(47.24,86.08) 47.24,89.76 47.62,90.14 48.11,90.14 v1(48.72,89.54)
  LYR4 w0.381: P9.32 58.55,70.21 58.55,72.37 57.05,73.86 55.47,73.86 54.48,74.85 51.36,74.85 49.78,76.43 49.78,79.76 47.24,82.3 v1(47.24,83.54)
  BOTTOM w0.381: FB2.1 47.75,82.27 47.24,82.78 v1(47.24,83.54)
VDD_CORE: length 46.3
  TOP w0.254: U5.K6 v1(50.32,95.14) U5.L6 ; U5.L7 v1(48.72,95.14) U5.K8 ; U5.J12 v1(44.72,93.54) ; v1(48.72,95.94) U5.L8 ; U5.G10 v1(46.32,92.74) ; U5.M11 v1(46.32,95.94) ; v1(47.92,95.94) U5.L9 ; U5.N12 v1(44.72,96.74) U5.N13 ; U5.F6 v1(50.32,91.94) U5.G6 ; U5.M13 v1(43.92,96.74) ; U5.H11 v1(45.52,92.74) ; U5.F7 v1(49.52,91.14) ; U5.N9 v1(47.92,97.54) U5.N8 ; v1(49.52,91.94) U5.G7 ; U5.K12 v1(45.52,95.14)
  LYR4 w0.508: v1(33.53,90.53) v1(33.53,89.89) 33.53,88.7 32.13,87.3 32.13,84.3 32.51,83.92 32.51,80.11 v1(30.61,78.21) v1(29.97,78.21)
  BOTTOM w0.305: C50.1 48.83,91.14 v1(49.52,91.14) v1(49.52,91.94) v1(50.32,91.94) ; C41.1 43.92,97.43 v1(43.92,96.74) v1(44.72,96.74) ; v1(46.32,92.74) 46.42,92.63 C49.1 ; v1(47.92,95.94) 47.23,95.94 C47.1 47.01,95.94 v1(46.32,95.94) ; v1(45.52,92.74) v1(44.72,93.54) 45.01,93.83 C46.1 45.01,94.63 v1(45.52,95.14) ; C45.1 40.26,94.97 41.22,95.94 v1(41.52,95.94) ; C48.1 48.32,94.44 U5.K8 v1(48.72,95.14) v1(50.32,95.14) ; C42.1 47.22,97.94 47.52,97.94 v1(47.92,97.54) ; C43.1 v1(48.72,95.94)
  BOTTOM w0.381: v1(40.72,91.94) C54.1 C44.1 ; v1(29.97,78.21) 29.97,78.91 L3.2 30.61,78.91 v1(30.61,78.21) v1(29.97,78.21)
  vias: v1(36.96,92.49) v1(36.96,91.73)
VDD_MPU: length 28.7
  TOP w0.254: U5.J13 v1(43.92,93.54) U5.H13 44.21,93.03 44.21,92.44 U5.G13 v1(43.92,91.94) U5.F13 v1(44.72,91.14) U5.F12 U5.F11 45.98,91.6 46.65,91.6 U5.F10
  TOP w0.635: 27.69,76.43 31.88,76.43 34.54,79.1 34.54,82.91 36.32,84.68 36.32,86.21 36.8,86.69
  BOTTOM w0.305: v1(44.72,91.14) 44.82,91.03 C63.1
  BOTTOM w0.381: C62.2 36.58,86.97 36.83,87.22 v1(37.48,87.22) v1(37.48,86.59) 36.7,86.59 C62.2 ; C62.2 36.2,86.33 C64.1 ; v1(43.92,93.54) 44.02,93.64 C65.1
  vias: v1(27.88,75.03) v1(28.51,75.03)
VDD_MPUON: length 10.6
  TOP w0.121: U5.A2 53.12,85.8 53.72,85.19 53.72,84.43 54.1,84.05 54.61,84.05 55.88,82.78 55.88,81.89 56.39,81.38 56.97,81.38 57.66,80.68 TP2.1
VDD_PHYA: length 6.9
  TOP w0.254: v1(22.67,98.15) 22.67,97.89 23.18,97.38 23.18,97.21 23.39,96.99 U14.27 ; v1(24.31,92.99) 24.73,93.41 U14.1
  BOTTOM w0.381: R137.2 v1(12.06,94.34) ; R122.2 v1(20.13,96.24) ; R120.2 v1(20.13,94.34) ; R123.2 v1(20.13,97.19) ; R121.2 v1(20.13,95.29)
VDD_PLL: length 12.9
  TOP w0.254: U5.R10 46.72,98.75 v1(46.32,99.14) U5.R11 v1(45.52,98.34) ; v1(49.52,90.34) U5.E7 ; U5.H15 v1(42.32,92.74)
  LYR3 w0.381: v1(46.32,99.14) v1(45.52,98.34) 44.69,97.51 43.05,97.51 42.62,97.08 42.61,97.08 42.54,97.01 41.5,97.01 41.25,96.75 41.25,96.52 40.91,96.18 40.47,96.18 v1(39.92,96.74)
  BOTTOM w0.305: C94.1 v1(45.52,98.34)
  BOTTOM w0.635: FB1.2 39.32,96.74 v1(39.92,96.74)
VDD_RTC: length 5.4
  TOP w0.254: v1(50.32,89.54) U5.D6
  BOTTOM w0.121: C104.1 50.15,85.78 50.15,87.42 50.72,87.99 50.72,88.66 50.72,89.13 v1(50.32,89.54)
VDDS: length 45.9
  TOP w0.254: v1(47.92,98.34) U5.P9 ; v1(47.92,91.14) U5.F9 ; U5.N6 v1(49.52,96.74) ; v1(44.72,95.14) U5.K13 ; v1(43.12,98.34) U5.P14 ; U5.E14 v1(43.12,90.34) ; U5.E6 v1(50.32,90.34)
  LYR5_PWR w0.305: v1(47.12,94.34) 46.86,94.59 45.26,94.59 v1(44.72,95.14)
  BOTTOM w0.121: 42.72,100.39 42.72,98.74
  BOTTOM w0.254: 42.72,98.74 v1(43.12,98.34)
  BOTTOM w0.305: C80.1 42.85,101.3 42.85,100.52 42.72,100.39
  BOTTOM w0.381: 48.15,101.43 48.15,101.56 48.04,101.66 48,101.66 47.75,101.91 47.75,102.07 46.74,103.08 43.53,103.08 43.31,102.86 43.31,101.7 43.03,101.43 C80.1 ; R8.2 R9.1 17.78,84.51 18.06,84.79 18.39,84.79 22.62,89.02 33.51,89.02 34.42,88.11 37.72,88.11 39.23,86.6 40.28,86.6 40.64,86.97 40.64,87.86
VDDS_DDR: length 54.9
  TOP w0.254: U5.H5 v1(51.12,93.54) U5.J5 ; v1(67.7,88.29) U12.K8 ; v1(68.5,90.69) U12.H9 ; v1(62.9,93.09) U12.D2 ; v1(68.5,93.89) U12.D9 ; U5.G5 v1(51.12,91.94) U5.F5 U5.E5 ; v1(62.1,88.29) U12.K2 ; U5.L5 v1(51.12,95.14) U5.K5 ; v1(68.5,93.09) U12.E9 ; v1(61.3,84.29) U12.R1 ; v1(68.5,85.89) U12.N9 ; v1(62.1,95.49) U12.B2 ; v1(61.3,96.29) U12.A1 ; v1(66.9,91.49) U12.G7 ; v1(67.7,96.29) U12.A8 ; v1(61.3,92.29) U12.F1 ; v1(68.5,84.29) U12.R9 ; v1(68.5,94.69) U12.C9 ; v1(61.3,85.89) U12.N1 ; v1(61.3,94.69) U12.C1
  TOP w0.305: v1(62.1,90.69) U12.H2
  TOP w0.381: v1(24,72.36) 24,73.38 C9.2 24.64,73.25 v1(24.64,72.36) ; C96.2 v1(56.77,80.94)
  BOTTOM w0.305: C97.1 51.12,95.83 v1(51.12,95.14) 51.12,94.44 C98.1 51.12,94.23 v1(51.12,93.54) 51.12,92.84 C99.1 51.12,92.63 v1(51.12,91.94) 51.12,91.24 C100.1
  BOTTOM w0.381: C102.1 C103.1 56.64,80.81 v1(56.77,80.94) ; v1(61.3,85.89) C112.1 ; v1(68.5,84.29) C121.1 ; C111.1 60.88,87.73 61.54,87.73 v1(62.1,88.29) ; R97.1 v1(65.41,83.49) ; C116.1 68.69,93.7 v1(68.5,93.89) ; v1(54.23,85.45) v1(54.23,84.68) 54.99,84.68 C95.2 54.99,85.45 v1(54.23,85.45) ; v1(54.23,85.45) 53.59,85.45 C101.1 ; v1(66.9,91.49) 66.1,90.69 R98.1 ; C110.1 60.55,90.69 61.08,91.22 61.52,91.22 61.53,91.21 61.58,91.21 v1(62.1,90.69) ; C114.1 v1(67.7,96.29) ; v1(68.5,94.69) C115.1 ; v1(67.7,88.29) 68.9,89.49 C119.1 ; v1(68.5,85.89) C120.1 ; C113.1 v1(61.3,84.29) ; v1(68.5,93.09) 68.5,92.51 68.83,92.18 C118.2 69.72,92 69.37,91.64 69.37,90.79 C117.1 v1(68.5,90.69) ; C107.1 v1(61.3,96.29) ; C109.1 v1(61.3,92.29) ; C122.2 v1(67.44,81.95) ; v1(61.3,94.69) C108.1
  vias: v1(20.24,72.11) v1(21.26,72.21) v1(51.31,71.09) v1(51.94,71.09) v1(55.12,71.09) v1(55.75,71.09) v1(59.31,71.09) v1(60.07,71.09) v1(60.83,71.09)
AIN0: length 38.3
  TOP w0.121: U5.B6 49.52,87.94 49.52,87.29 49.91,86.89 49.91,85.57 49.26,84.92 49.26,75.18 49.66,74.78 60.58,74.78 64.01,71.35 66.8,71.35 68.07,70.08 68.07,68.3 P9.39
AIN1: length 32
  TOP w0.121: v1(49.52,88.73) U5.C7
  LYR4 w0.133: P9.40 67.69,71.22 63.6,71.22 58.93,75.9 58.93,81.51 56.16,84.28 54,84.28 52.58,85.7 51.82,85.7 49.91,87.6 49.91,88.34 v1(49.52,88.73)
AIN2: length 36.8
  TOP w0.121: P9.37 65.66,68.17 65.66,70.21 65.02,70.84 63.5,70.84 60.07,74.27 49.15,74.27 48.76,74.66 48.76,85.19 49.4,85.83 49.4,86.64 48.72,87.33 48.72,87.94 U5.B7
AIN3: length 33.1
  TOP w0.121: P9.38 65.28,71.09 63.75,71.09 60.32,74.52 49.4,74.52 49.01,74.92 49.01,85.05 49.66,85.71 49.66,86.76 49.12,87.31 U5.A7
AIN4: length 31.1
  TOP w0.121: U5.C8 v1(48.72,88.73)
  LYR4 w0.133: v1(48.72,88.73) 49.53,87.92 49.53,86.46 50.67,85.32 52.56,85.32 53.93,83.95 54.59,83.95 54.74,83.79 56.2,83.79 58.55,81.45 58.55,75.59 62.99,71.15 62.99,68.3 P9.33
AIN5: length 32.4
  TOP w0.121: P9.36 63.83,69.57 59.64,73.76 48.64,73.76 48.26,74.14 48.26,86.97 47.92,87.31 47.92,87.94 U5.B8
AIN6: length 35.8
  TOP w0.121: U5.A8 48.32,87.29 49.15,86.46 49.15,85.95 48.51,85.32 48.51,74.4 48.89,74.02 59.82,74.02 63.25,70.59 64.77,70.59 65.28,70.08 65.28,68.05 P9.35
AIN7: length 10.4
  TOP w0.121: U5.C9 v1(47.92,88.74)
  LYR4 w0.133: v1(47.92,88.73) 49.15,87.5 49.15,83.54 49.56,83.13 49.63,83.13 v1(49.66,83.1)
  BOTTOM w0.121: R164.1 50.16,80.81 49.97,81 49.97,81.64 49.78,81.83 R163.2 49.34,82.72 49.66,83.03 v1(49.66,83.1)
B_UART0_RX: length 13.6
  TOP w0.121: J1.4 50.42,71.6 48.51,71.6 47.75,72.36 R165.1
  BOTTOM w0.121: U15.2 53.33,76.31 53.59,76.05 53.59,74.78 J1.4
B_UART0_TX: length 5.2
  BOTTOM w0.121: J1.5 54.1,73.76 53.85,74.02 53.85,76.3 53.35,76.8 U15.3
CAP_VBB_MPU: length 4.2
  TOP w0.121: v1(46.32,88.73) 46.33,88.75 U5.C10
  BOTTOM w0.121: C91.1 46.8,87.54 46.32,88.02 v1(46.32,88.73)
CAP_VDD_SRAM_CORE: length 5.2
  TOP w0.121: U5.D9 v1(47.92,89.54)
  BOTTOM w0.121: v1(47.92,89.54) 48.32,89.13 48.32,88.17 47.75,87.6 C89.1
CAP_VDD_SRAM_MPU: length 5
  TOP w0.121: v1(45.52,89.54) U5.D11
  BOTTOM w0.121: v1(45.52,89.54) 45.92,89.13 45.92,85.39 C90.1
CLKOUT2: length 55.5
  BOTTOM w0.121: P2.18 37.4,82.59 37.07,82.92 37.07,85.1 37.68,85.72 41.29,85.72 41.53,85.95 42.29,85.95 42.48,85.76 42.48,84.81 R19.2 R20.1 43.94,83.67 42.99,82.72 42.99,80.07 44.28,78.78 48.1,78.78 48.28,78.96 61.39,78.96 68.75,71.6 71.37,71.6 73.03,69.95 73.03,68.17 P9.41
CLKOUT_SRC: length 5.1
  TOP w0.121: U5.D14 v1(43.12,89.54)
  BOTTOM w0.121: v1(43.12,89.54) 42.72,89.13 42.72,88.39 42.99,88.11 R19.1
CRS: length 2.7
  TOP w0.121: R139.2 30.91,97.36 30.32,97.36 29.95,96.99 U14.14
DDR_A0: length 23.9
  TOP w0.121: U5.F3 v1(52.72,91.14) ; v1(62.9,85.89) U12.N3
  LYR3 w0.133: v1(55.24,88.24) 54.74,88.24 54.61,88.11 54.61,86.33 56.26,84.68 56.26,84.43 58.42,82.27 62.99,82.27 63.75,83.03 63.75,85.83 63.37,86.21 63.21,86.21 v1(62.9,85.89)
  BOTTOM w0.121: v1(55.24,88.24) 53.98,89.51 53.98,91.29 53.72,91.54 53.12,91.54 v1(52.72,91.14)
DDR_A1: length 24.1
  TOP w0.121: v1(60.32,89) 60.32,89.89 59.12,91.1 57.98,91.1 55.94,93.14 U5.H1 ; v1(66.9,85.09) U12.P7
  LYR3 w0.121: 61.59,89 61.9,88.69 63.07,88.69
  LYR3 w0.133: v1(66.9,85.09) 66.54,85.45 66.29,85.45 66.17,85.32 66.17,84.81 66.04,84.68 65.79,84.68 65.66,84.81 65.66,85.32 65.53,85.45 65.41,85.45 65.28,85.32 65.28,84.43 65.41,84.3 65.79,84.3 65.91,84.18 65.91,84.02 65.79,83.9 65.02,83.9 64.9,84.02 64.9,85.57 65.28,85.95 65.28,86.97 64.01,88.24 63.63,88.24 63.18,88.69 63.07,88.69 ; v1(60.32,89) 60.33,89 61.59,89
DDR_A2: length 23.9
  TOP w0.121: U5.E4 v1(51.92,90.34) ; v1(62.9,85.09) U12.P3
  LYR3 w0.121: 62.5,87.21 62.5,85.49 v1(62.9,85.09)
  LYR3 w0.133: 62.5,87.21 62.23,87.48 60.83,87.48 60.45,87.1 58.17,87.1 58.04,87.22 58.04,88.62 58.17,88.75 58.8,88.75 58.9,88.85 58.9,89.28 58.8,89.38 58.17,89.38 58.04,89.51 58.04,90.53 56.11,92.45 55.9,92.45 55.65,92.2 55.65,92.02 56.52,91.16 56.52,90.27 55.75,89.51 52.52,89.51 51.92,90.11 v1(51.92,90.34)
DDR_A3: length 24
  TOP w0.121: v1(52.72,88.73) U5.C3 ; v1(62.1,85.89) U12.N2
  LYR3 w0.121: v1(62.1,85.89) 61.7,86.29 61,86.29
  LYR3 w0.133: 61,86.29 60.96,86.33 57.4,86.33 57.28,86.46 57.28,89.56 57.2,89.64 56.97,89.64 56.9,89.56 56.9,87.32 56.82,87.25 56.46,87.25 56.39,87.17 56.39,86.79 56.31,86.72 56.08,86.72 56.01,86.79 56.01,87.17 55.93,87.25 55.77,87.25 55.69,87.32 55.69,87.53 55.77,87.6 56.44,87.6 56.52,87.68 56.52,87.91 56.44,87.99 55.77,87.99 55.69,88.06 55.69,88.29 55.77,88.37 56.44,88.37 56.52,88.44 56.52,88.66 56.44,88.73 54.36,88.73 54.23,88.61 54.23,87.48 54.1,87.35 53.85,87.35 53.72,87.48 53.72,88.61 53.59,88.73 v1(52.72,88.73)
DDR_A4: length 23.9
  TOP w0.121: v1(67.7,85.09) U12.P8 ; U5.C2 53.51,88.74 53.51,88.18 53.75,87.94 54.08,87.94 54.36,87.66 54.36,86.46 55.12,85.7 55.12,84.94 57.91,82.14 57.91,81.76 v1(57.53,81.38)
  LYR3 w0.121: v1(67.7,85.09) 67.3,84.69 66.68,84.69
  LYR3 w0.133: v1(57.53,81.38) 57.78,81.13 63.75,81.13 64.52,81.89 66.17,81.89 66.42,82.14 66.42,84.43 66.68,84.69
DDR_A5: length 23.9
  TOP w0.121: v1(62.1,85.09) U12.P2 ; v1(55.24,87.22) 54.86,87.22 54.74,87.35 54.74,87.73 54.13,88.34 U5.B1
  LYR3 w0.121: v1(62.1,85.09) 62.5,84.69 62.5,83.3 62.48,83.29
  LYR3 w0.133: v1(55.24,87.22) 55.69,86.78 55.69,86.33 55.94,86.08 56.57,86.08 56.64,86.16 56.64,86.77 56.72,86.84 56.95,86.84 57.02,86.77 57.02,84.81 57.15,84.68 57.4,84.68 57.53,84.81 57.53,85.83 57.66,85.95 57.91,85.95 58.04,85.83 58.04,83.67 58.29,83.41 58.93,83.41 59.05,83.54 59.05,85.83 59.18,85.95 60.58,85.95 60.71,85.83 60.71,83.16 60.83,83.03 62.23,83.03 62.48,83.29
DDR_A6: length 24.1
  TOP w0.121: v1(67.7,84.29) U12.R8 ; v1(51.12,89.54) U5.D5
  BOTTOM w0.121: v1(67.7,84.29) 67.3,83.89 67.3,83.27 65.91,81.89 58.67,81.89 56.77,83.79 56.77,86.33 55.37,87.73 54.99,87.73 52.79,89.93 51.52,89.93 v1(51.12,89.54)
DDR_A7: length 24.1
  TOP w0.121: U5.E2 53.52,91.14 55.52,91.14 55.75,90.91 55.75,90.27 57.02,89 57.02,84.81 58.8,83.03 59.56,83.03 59.69,83.16 59.69,84.43 59.56,84.56 59.03,84.56 v1(58.55,85.04) ; v1(62.1,84.29) U12.R2
  BOTTOM w0.121: v1(62.1,84.29) U12.R2 63.63,84.69 63.75,84.82 63.75,85.36 63.63,85.49 61,85.49 60.55,85.04 v1(58.55,85.04)
DDR_A8: length 23.9
  TOP w0.121: v1(67.7,83.49) U12.T8 ; v1(51.92,89.54) U5.D4
  BOTTOM w0.121: v1(51.92,89.54) 52.68,89.54 53.34,88.87 53.34,86.44 53.59,86.19 56.01,86.19 56.39,85.81 56.39,83.67 58.55,81.51 66.04,81.51 67.7,83.17 v1(67.7,83.49)
DDR_A9: length 24
  TOP w0.121: v1(62.9,84.29) U12.R3 ; v1(55.24,86.59) 55.24,86.07 55.36,85.95 55.53,85.95 55.64,86.07 55.64,87.59 55.5,87.73 55.19,87.73 54.48,88.44 54.48,88.57 U5.C1
  LYR3 w0.133: v1(55.24,86.59) 55.24,86.21 55.75,85.7 56.39,85.7 56.64,85.45 56.64,84.56 58.55,82.65 59.44,82.65 59.56,82.78 59.56,85.45 59.69,85.57 60.07,85.57 60.2,85.45 60.2,82.78 60.32,82.65 62.87,82.65 63.37,83.16 63.37,84.56 63.25,84.68 63.02,84.68 62.9,84.56 v1(62.9,84.29)
DDR_A10: length 24
  TOP w0.121: U5.F4 v1(51.92,91.14) ; v1(66.9,87.49) U12.L7
  LYR3 w0.121: v1(51.92,91.14) 52.32,91.54 53.08,91.54
  LYR3 w0.133: v1(66.9,87.49) 67.18,87.78 67.18,87.99 67.06,88.11 66.17,88.11 66.04,88.24 66.04,88.49 66.17,88.62 67.06,88.62 67.18,88.75 67.18,89 67.06,89.13 65.79,89.13 63.75,91.16 60.71,91.16 59.12,92.75 58.23,92.75 57.14,93.83 53.98,93.83 53.59,93.45 53.59,92.05 53.08,91.54
DDR_A11: length 23.9
  TOP w0.121: U5.F2 53.52,91.94 v1(55.24,91.94) ; v1(66.9,84.29) U12.R7
  BOTTOM w0.121: v1(55.24,91.94) 54.74,91.43 54.74,89.89 56.01,88.62 57.28,88.62 57.53,88.37 57.53,84.05 58.93,82.65 65.53,82.65 66.17,83.29 66.17,84.04 66.42,84.29 v1(66.9,84.29)
DDR_A12: length 24.1
  TOP w0.121: v1(52.72,90.34) U5.E3 ; v1(66.9,85.89) U12.N7
  LYR3 w0.133: v1(52.72,90.34) 52.78,90.27 55.5,90.27 55.75,90.53 55.75,90.91 55.5,91.16 54.61,91.16 54.36,91.41 54.36,92.81 54.61,93.07 56.52,93.07 58.04,91.54 59.31,91.54 60.95,89.9 62.62,89.9 62.87,90.14 63.63,90.14 65.28,88.49 65.28,87.51 v1(66.9,85.89)
DDR_A13: length 24
  TOP w0.121: U5.H3 v1(52.72,92.74) ; v1(62.9,83.49) U12.T3
  BOTTOM w0.121: v1(62.9,83.49) 64.77,83.49 64.9,83.36 64.9,83.16 64.77,83.03 59.05,83.03 57.91,84.18 57.91,88.75 57.66,89 56.13,89 55.75,89.38 55.75,92.3 55.32,92.74 v1(52.72,92.74)
DDR_A14: length 24
  TOP w0.121: v1(66.9,83.49) U12.T7 ; v1(51.92,92.74) U5.H4
  BOTTOM w0.121: v1(66.9,83.49) 65.68,82.27 58.8,82.27 57.15,83.92 57.15,86.97 54.36,89.76 54.36,91.92 53.94,92.34 52.29,92.34 51.92,92.71 v1(51.92,92.74)
DDR_A15: length 24
  TOP w0.121: U5.D3 52.72,89.53 54.97,89.53 56.01,88.49 56.01,84.53 58.75,81.79 64.47,81.79 65.91,83.24 65.91,86.51 U12.M7
DDR_BA0: length 24.1
  TOP w0.121: U5.C4 v1(51.92,88.73) ; v1(62.1,86.69) U12.M2
  LYR3 w0.121: 51.52,87.6 51.52,88.61 51.64,88.73 v1(51.92,88.73) ; 52.32,88.87 52.32,87.6
  LYR3 w0.133: 52.32,88.87 52.32,89.01 52.44,89.14 55.89,89.14 56.9,90.14 56.9,90.78 56.99,90.88 57.18,90.88 57.66,90.4 57.66,87.1 58.04,86.72 60.58,86.72 60.96,87.1 61.97,87.1 62.1,86.97 v1(62.1,86.69) ; 51.52,87.6 51.52,86.59 51.64,86.46 51.82,86.46 51.94,86.59 51.94,86.97 52.07,87.1 52.32,87.1 52.45,86.97 52.45,86.59 52.58,86.46 52.83,86.46 52.96,86.59 52.96,87.35 52.83,87.48 52.44,87.48 52.32,87.6
DDR_BA1: length 24.1
  TOP w0.121: v1(67.7,85.89) U12.N8 ; U5.E1 v1(55.24,90.74)
  LYR3 w0.133: v1(67.7,85.89) 67.22,86.37 67.22,86.78 67.06,86.94 66.45,86.94 65.63,87.76 65.63,88.65 63.5,90.78 62.74,90.78 62.61,90.65 62.61,90.4 62.48,90.27 61.09,90.27 59.47,91.88 58.33,91.88 56.77,93.45 54.23,93.45 53.98,93.19 53.98,91.67 53.72,91.41 53.72,91.03 54.02,90.74 v1(55.24,90.74)
DDR_BA2: length 24.1
  TOP w0.121: v1(52.72,87.93) U5.B3 ; v1(62.9,86.69) U12.M3
  LYR3 w0.133: v1(62.9,86.69) 63.37,86.69 63.5,86.82 63.5,87.22 63.63,87.35 63.88,87.35 64.14,87.1 64.14,86.72 63.88,86.46 63.88,86.21 64.14,85.95 64.14,82.65 63.37,81.89 58.29,81.89 55.88,84.3 55.88,84.56 54.1,86.33 53.91,86.33 53.78,86.21 53.78,85.95 53.66,85.83 53.47,85.83 53.34,85.95 53.34,88.11 53.21,88.24 53.02,88.24 v1(52.72,87.93)
DDR_CASN: length 24
  TOP w0.121: v1(58.55,87.6) 58.55,86.84 58.67,86.72 59.56,86.72 59.69,86.59 59.69,86.08 59.56,85.95 59.44,85.95 59.31,85.83 59.31,85.57 59.44,85.45 59.56,85.45 59.69,85.32 59.69,85.06 59.56,84.94 59.07,84.94 58.95,85.06 58.95,86.33 58.82,86.46 58.17,86.46 58.04,86.33 58.04,84.94 57.91,84.81 57.53,84.81 57.4,84.94 57.4,89.76 57.28,89.89 56.77,89.89 56.13,90.53 56.13,91.28 55.88,91.54 U5.F1 ; v1(62.9,88.29) U12.K3
  LYR3 w0.133: v1(62.9,88.29) 62.46,87.86 60.71,87.86 60.45,87.6 v1(58.55,87.6)
DDR_CKE: length 25.1
  TOP w0.121: U5.G3 v1(52.72,91.94) ; v1(68.5,88.29) U12.K9
  LYR3 w0.133: v1(68.5,88.29) 68.71,88.5 68.71,89.38 68.58,89.51 66.04,89.51 64.01,91.54 60.83,91.54 59.31,93.07 58.42,93.07 57.28,94.21 54.61,94.21 54.23,94.59 52.58,94.59 52.45,94.46 52.45,94.21 52.58,94.08 53.09,94.08 53.21,93.95 53.21,92.43 v1(52.72,91.94)
  BOTTOM w0.121: R96.2 v1(68.5,88.29)
DDR_CLK: length 24
  TOP w0.095: U12.J7 66.33,89.33 66.14,89.33 65.15,88.34 65.15,84.82 62.98,82.65 58.82,82.65 56.67,84.8 56.67,88.85 55.19,90.32 53.76,90.32 53.37,89.94 U5.D2
DDR_CLKN: length 24
  TOP w0.095: U12.K7 66.77,88.69 66.87,88.79 66.87,88.94 66.77,89.05 66.25,89.05 65.43,88.23 65.43,84.71 63.09,82.37 58.7,82.37 56.39,84.68 56.39,88.73 55.08,90.04 54.02,90.04 U5.D1
DDR_CSN: length 23.9
  TOP w0.121: U5.H2 53.52,93.54 56.04,93.54 58.1,91.48 59.25,91.48 60.83,89.89 60.83,88.57 60.76,88.49 60.27,88.49 60.2,88.42 60.2,87.22 60.45,86.97 60.45,83.54 60.57,83.41 60.71,83.41 60.83,83.54 60.83,87.1 60.58,87.35 60.58,87.91 60.66,87.99 60.88,87.99 60.96,87.91 60.96,87.56 61.04,87.49 62.09,87.49 U12.L2
DDR_D0: length 23.3
  TOP w0.121: v1(63.7,93.09) U12.E3 ; v1(52.72,96.74) U5.M3
  LYR3 w0.133: v1(63.7,93.09) 63.7,94.84 63.82,94.97 64.26,94.97 64.39,94.84 64.39,92.56 64.52,92.43 65.02,92.43 65.15,92.56 65.15,94.72 61.85,98.02 54.36,98.02 53.07,96.74 v1(52.72,96.74)
DDR_D1: length 23.3
  TOP w0.121: v1(66.9,92.29) U12.F7 ; v1(51.92,96.74) U5.M4
  LYR3 w0.121: v1(66.9,92.29) 67.3,91.89 67.86,91.89 68.1,91.66 68.1,90.87 68.1,90.52 67.87,90.28 ; v1(51.92,96.74) 52.32,96.34 52.32,95.77 52.55,95.54 54.17,95.54
  LYR3 w0.133: 54.17,95.54 55.12,94.59 57.66,94.59 58.17,94.08 58.8,94.08 61,91.88 64.3,91.88 66.29,89.9 67.48,89.9 67.87,90.28
DDR_D2: length 23.3
  TOP w0.121: U5.N1 56.89,97.14 57.28,96.75 58.42,96.75 58.55,96.88 58.55,97.76 58.42,97.89 56.26,97.89 56.13,98.02 56.13,98.27 56.26,98.4 62.48,98.4 62.61,98.27 62.61,97.26 64.13,95.74 64.13,92.56 63.86,92.29 63.38,92.29 63.37,92.29 62.9,92.29 U12.F2
DDR_D3: length 23.3
  TOP w0.121: U5.N2 53.52,97.54 57.25,97.54 v1(57.53,97.26) ; v1(67.7,92.29) U12.F8
  BOTTOM w0.121: v1(57.53,97.26) 62.23,97.26 63.75,95.73 63.75,94.21 64.58,93.38 64.58,92.81 64.71,92.68 64.9,92.68 65.02,92.81 65.02,93.7 65.15,93.83 65.41,93.83 65.53,93.7 65.53,92.81 65.66,92.68 65.91,92.68 66.04,92.81 66.04,93.7 66.17,93.83 66.97,93.83 67.31,93.49 67.9,93.49 68.1,93.29 68.1,92.69 v1(67.7,92.29)
DDR_D4: length 23.3
  TOP w0.121: U12.H3 64.92,90.29 65.66,91.03 65.66,96.88 64.77,97.76 v1(63.75,97.76) ; U5.N3 v1(52.72,97.54)
  LYR3 w0.133: v1(63.75,97.76) 62.74,98.78 53.98,98.78 52.73,97.54 v1(52.72,97.54)
DDR_D5: length 23.3
  TOP w0.121: U5.N4 v1(51.92,97.54) ; v1(67.7,90.69) U12.H8
  LYR3 w0.121: 52.97,97.14 52.32,97.14 v1(51.92,97.54)
  LYR3 w0.133: 52.97,97.14 54.23,98.4 62.1,98.4 65.66,94.84 65.66,91.16 66.55,90.27 67.28,90.27 v1(67.7,90.69)
DDR_D6: length 23.3
  TOP w0.121: U12.G2 62.9,90.69 64.81,90.69 65.28,91.16 65.28,96.37 v1(64.39,97.26) ; U5.P3 v1(52.72,98.34)
  LYR3 w0.133: v1(52.72,98.34) 53.02,98.34 53.85,99.16 62.99,99.16 64.39,97.76 v1(64.39,97.26)
DDR_D7: length 23.3
  TOP w0.121: U5.P4 v1(51.92,98.34) ; v1(66.9,90.69) U12.H7
  LYR3 w0.121: 53.02,98.74 52.32,98.74 v1(51.92,98.34)
  LYR3 w0.133: v1(66.9,90.69) 66.17,91.42 66.17,96.62 63.27,99.52 53.8,99.52 53.02,98.74
DDR_D8: length 20.3
  TOP w0.121: U12.D7 66.04,93.03 66.04,89.89 64.39,88.24 63.88,88.24 63.75,88.37 63.75,89.76 63.63,89.89 61.34,89.89 60.77,90.46 60.77,91.35 60.26,91.86 58.23,91.86 56.15,93.94 U5.J1
DDR_D9: length 20.3
  TOP w0.121: v1(57.53,95.1) 57.17,94.74 U5.K1 ; v1(62.9,94.69) U12.C3
  LYR3 w0.133: v1(57.53,95.1) 57.91,95.1 58.04,95.22 58.04,97.13 58.17,97.26 58.93,97.26 59.05,97.13 59.05,94.97 59.18,94.84 59.69,94.84 59.82,94.97 59.82,97.13 59.94,97.26 60.45,97.26 60.58,97.13 60.58,93.95 60.71,93.83 62.77,93.83 62.9,93.95 v1(62.9,94.69)
DDR_D10: length 20.3
  TOP w0.121: v1(67.7,94.69) U12.C8 ; U5.K2 53.52,95.14 v1(55.24,95.14)
  BOTTOM w0.121: v1(55.24,95.14) 55.72,95.14 55.88,94.97 56.52,94.97 56.64,95.1 56.64,97.26 57.15,97.76 62.23,97.76 64.14,95.86 64.14,94.46 64.39,94.21 67.21,94.21 v1(67.7,94.69)
DDR_D11: length 20.1
  TOP w0.121: v1(52.72,95.14) U5.K3 ; v1(62.1,94.69) U12.C2
  BOTTOM w0.121: v1(62.1,94.69) 62.39,94.39 62.39,94.2 62.27,94.08 59.56,94.08 59.44,93.95 59.44,93.7 59.56,93.57 61.52,93.57 61.64,93.45 61.64,93.06 61.47,92.89 59.21,92.89 58.95,93.14 58.95,93.96 58.83,94.08 57.15,94.08 56.64,94.59 54.99,94.59 54.81,94.77 54.81,95.34 54.69,95.46 54.46,95.46 54.36,95.35 54.36,94.72 54.23,94.59 52.62,94.59 52.5,94.71 52.5,94.92 v1(52.72,95.14)
DDR_D12: length 20.2
  TOP w0.121: U5.K4 v1(51.92,95.14) ; v1(66.9,96.29) U12.A7
  BOTTOM w0.121: v1(66.9,96.29) 66.9,96.65 64.71,98.84 55.94,98.84 53.98,96.88 53.98,95.29 53.85,95.16 53.59,95.16 53.47,95.29 53.47,95.41 53.34,95.54 52.32,95.54 v1(51.92,95.14)
DDR_D13: length 20.2
  TOP w0.121: v1(52.72,95.94) U5.L3 ; v1(62.1,96.29) U12.A2
  LYR3 w0.133: v1(62.1,96.29) 62.1,96.3 62.1,97.13 61.57,97.66 54.61,97.66 54.48,97.54 54.48,97.13 54.61,97 56.9,97 57.02,96.88 57.02,95.22 56.9,95.1 55.88,95.1 55.75,95.22 55.75,96.24 55.63,96.37 53.47,96.37 53.04,95.94 v1(52.72,95.94)
DDR_D14: length 20.3
  TOP w0.121: U5.L4 v1(51.92,95.94) ; v1(67.7,95.49) U12.B8
  BOTTOM w0.121: v1(51.92,95.94) 52.32,96.34 52.93,96.34 55.75,99.16 64.9,99.16 67.3,96.76 67.3,95.89 v1(67.7,95.49)
DDR_D15: length 20.1
  TOP w0.121: U5.M1 54.74,96.34 56.26,96.34 56.39,96.21 56.39,95.99 56.26,95.86 55.88,95.86 55.75,95.73 55.75,95.35 55.88,95.22 56.9,95.22 57.02,95.35 57.02,95.61 57.15,95.73 60.71,95.73 60.83,95.86 60.83,96.11 60.71,96.24 59.44,96.24 59.31,96.37 59.31,96.62 59.44,96.75 60.71,96.75 60.83,96.88 60.83,97.13 60.71,97.26 59.44,97.26 59.31,97.38 59.31,97.64 59.44,97.76 61.42,97.76 U12.A3
DDR_DQM0: length 23.3
  TOP w0.121: U5.M2 53.52,96.74 56.65,96.74 57.1,96.29 v1(57.53,96.29) ; v1(66.9,93.09) U12.E7
  BOTTOM w0.121: v1(57.53,96.29) 57.15,96.29 57.02,96.16 57.02,94.72 57.15,94.59 57.91,94.59 58.04,94.72 58.04,96.75 58.17,96.88 62.1,96.88 63.37,95.61 63.37,94.08 64.14,93.32 64.14,92.43 64.26,92.3 66.29,92.3 66.42,92.43 66.42,92.96 66.55,93.09 v1(66.9,93.09)
DDR_DQM1: length 20.2
  TOP w0.121: U12.D3 62.9,93.89 61.4,93.89 60.83,93.32 59.18,93.32 59.05,93.45 59.05,93.7 59.18,93.83 60.71,93.83 60.83,93.95 60.83,94.21 60.71,94.34 59.18,94.34 59.05,94.46 59.05,94.72 59.18,94.84 60.71,94.84 60.83,94.97 60.83,95.22 60.71,95.35 58.17,95.35 58.04,95.22 58.04,94.46 57.91,94.34 53.52,94.34 U5.J2
